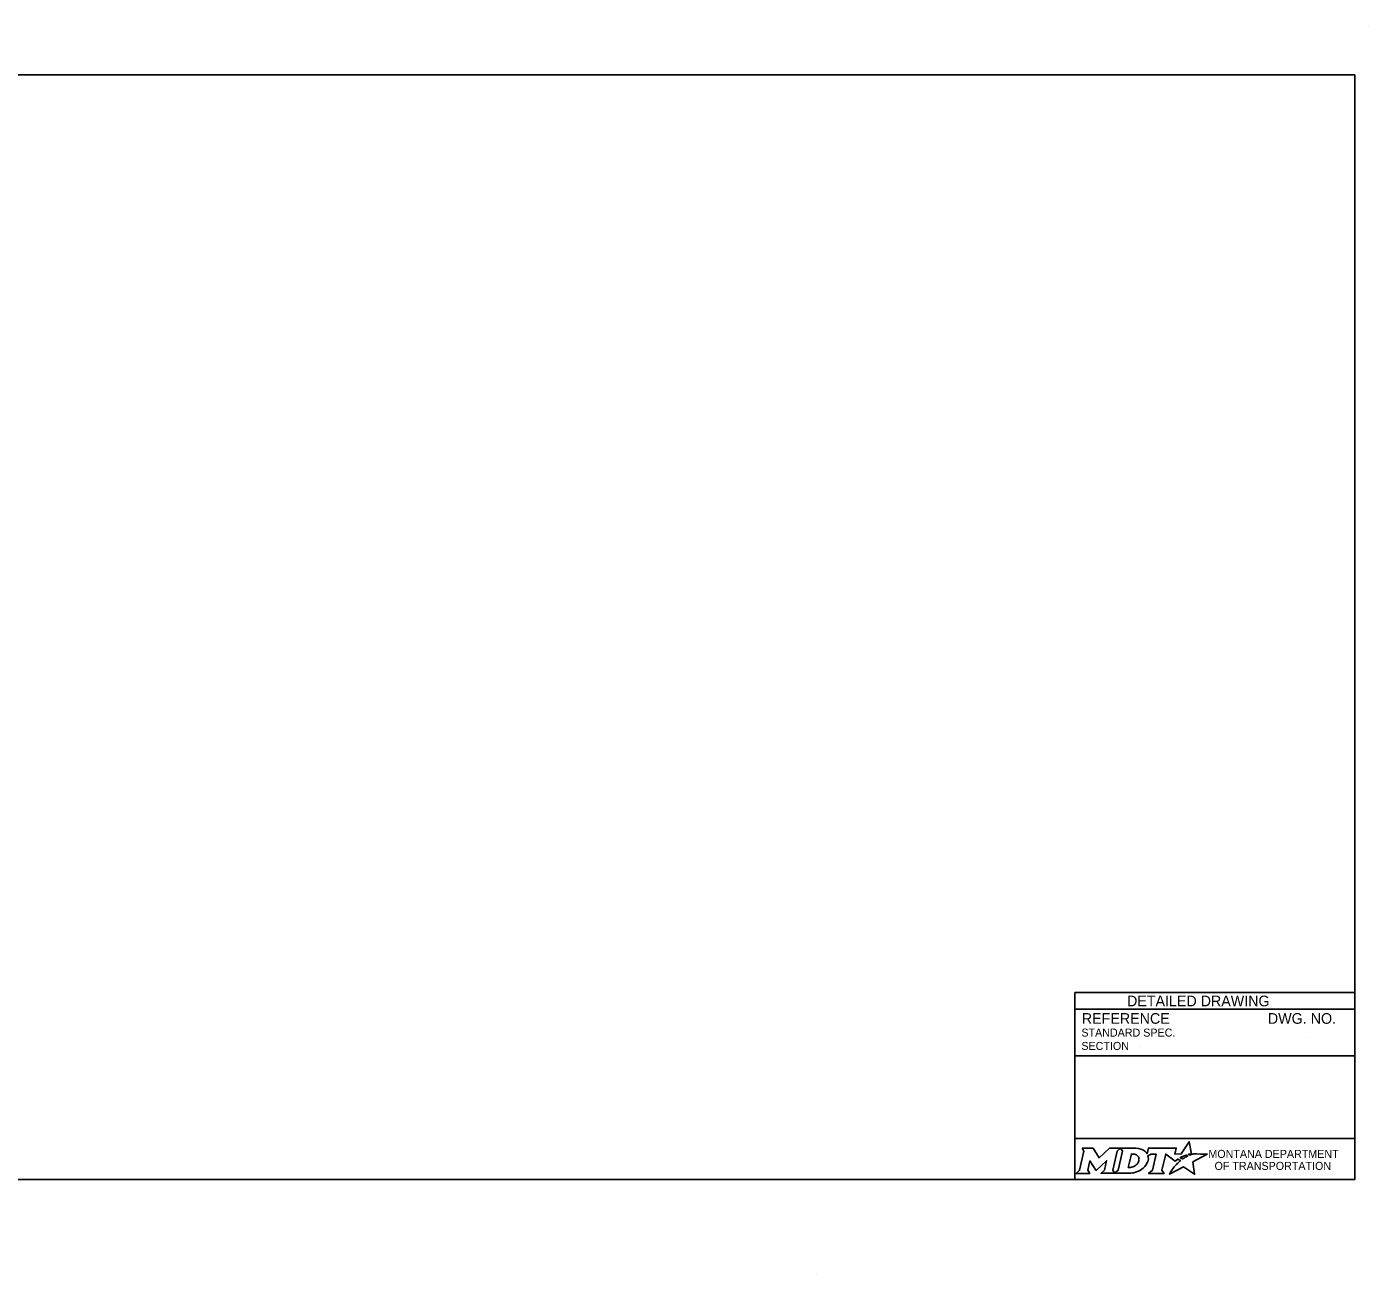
# Model space of a CAD drawing. Extents: x 49991.4 to 50021, y 49987.6 to 50011.4.
# Drawn here: x 50010.98 to 50021.04, y 49999.18 to 50008.52 of the extents above; entities that cross this region are included whole.
import ezdxf

# ---------------------------------------------------------------- set-up
doc = ezdxf.new("R2010")
doc.units = 0
for name, color, linetype in [('Default', 7, 'Continuous'), ('Level 1', 7, 'Continuous'), ('Level 4', 7, 'Continuous')]:
    doc.layers.add(name, color=color, linetype=linetype)

msp = doc.modelspace()

# ---------------------------------------------------------------- linework, layer by layer
at = {"layer": 'Default'}
for points in [[(50018.893, 50000.121), (50018.907, 50000.097), (50018.874, 49999.954), (50018.848, 49999.931), (50018.95, 49999.931), (50018.936, 49999.954), (50018.952, 50000.024), (50018.996, 49999.955), (50019.002, 49999.955), (50019.077, 50000.025), (50019.06, 49999.954), (50019.035, 49999.932), (50019.137, 49999.932), (50019.123, 49999.955), (50019.156, 50000.097)], [(50019.156, 50000.097), (50019.182, 50000.121), (50019.099, 50000.121), (50019.02, 50000.048), (50018.975, 50000.12), (50018.893, 50000.121)], [(50019.295, 50000.121), (50019.182, 50000.121), (50019.196, 50000.098), (50019.163, 49999.954), (50019.137, 49999.932), (50019.248, 49999.932)], [(50019.7, 50000.068), (50019.69, 50000.074), (50019.702, 50000.076), (50019.713, 50000.078), (50019.696, 50000.168), (50019.636, 50000.077), (50019.589, 50000.076), (50019.599, 50000.12), (50019.39, 50000.121), (50019.38, 50000.078), (50019.374, 50000.086)], [(50019.319, 50000.034), (50019.318, 50000.026), (50019.315, 50000.017), (50019.311, 50000.008), (50019.305, 50000.001), (50019.299, 49999.994), (50019.291, 49999.988), (50019.282, 49999.983), (50019.273, 49999.979), (50019.264, 49999.977), (50019.255, 49999.976), (50019.239, 49999.976), (50019.263, 50000.076), (50019.279, 50000.076), (50019.286, 50000.075), (50019.294, 50000.073), (50019.301, 50000.07), (50019.307, 50000.066), (50019.311, 50000.061), (50019.315, 50000.055), (50019.318, 50000.049), (50019.319, 50000.042), (50019.32, 50000.038), (50019.319, 50000.034)], [(50019.387, 50000.062), (50019.411, 50000.075), (50019.448, 50000.075), (50019.42, 49999.954), (50019.392, 49999.931), (50019.508, 49999.931), (50019.491, 49999.954), (50019.52, 50000.075), (50019.591, 50000.023), (50019.612, 50000.038), (50019.632, 50000.027)], [(50019.576, 49999.971), (50019.561, 49999.947), (50019.556, 49999.939), (50019.55, 49999.931), (50019.548, 49999.926), (50019.653, 49999.979), (50019.737, 49999.924), (50019.724, 50000.017), (50019.831, 50000.075), (50019.782, 50000.076), (50019.751, 50000.077), (50019.731, 50000.077), (50019.724, 50000.075), (50019.719, 50000.074), (50019.711, 50000.072), (50019.7, 50000.068)], [(50019.65, 50000.04), (50019.648, 50000.039), (50019.629, 50000.048), (50019.639, 50000.054), (50019.644, 50000.056), (50019.652, 50000.06), (50019.658, 50000.063), (50019.666, 50000.066), (50019.673, 50000.068), (50019.685, 50000.061), (50019.681, 50000.059), (50019.676, 50000.056), (50019.672, 50000.054), (50019.667, 50000.051), (50019.665, 50000.05), (50019.662, 50000.049), (50019.66, 50000.047), (50019.658, 50000.046), (50019.655, 50000.044), (50019.652, 50000.042), (50019.65, 50000.04)], [(50019.293, 49999.939), (50019.302, 49999.942), (50019.315, 49999.947), (50019.335, 49999.958)], [(50019.59, 49999.987), (50019.59, 49999.987)]]:
    msp.add_lwpolyline(points, dxfattribs=at)
for centre, radius, start, end in [((50019.319, 50000.042), 0.0709, 339.5329, 15.8582), ((50019.274, 50000.059), 0.118, 300.9103, 339.1383)]:
    msp.add_arc(centre, radius, start, end, dxfattribs=at)
for centre, major_axis, ratio, start_param, end_param in [((50019.293, 50000.073), (0.0834, -0.0037), 0.568097, 0.61298, 1.570796), ((50019.349, 50000.081), (0.0361, -0.0295), 0.469099, 1.225588, 1.570796), ((50019.621, 50000.017), (-0.0112, -0.0097), 0.021651, 3.157348, 6.283185), ((50019.248, 50000.08), (0, 0.148), 0.987302, 3.139398, 3.456847), ((50019.583, 49999.979), (-0.00694, -0.00806), 0.008222, 0, 3.137361), ((50019.6, 49999.997), (-0.0098, -0.0102), 0.016458, 3.141593, 6.279097)]:
    msp.add_ellipse(centre, major_axis=major_axis, ratio=ratio, start_param=start_param, end_param=end_param, dxfattribs=at)
at = {"layer": 'Level 1'}
for p, q in [((50021.038, 50008.524), (50021.038, 50008.524)), ((50016.9, 49999.176), (50016.9, 49999.176))]:
    msp.add_line(p, q, dxfattribs=at)
msp.add_lwpolyline([(50020.938, 50008.165), (50009.737, 50008.165), (50009.737, 49999.886), (50020.938, 49999.886)], close=True, dxfattribs=at)
at = {"layer": 'Level 4'}
for p, q in [((50020.938, 50001.286), (50018.838, 50001.286)), ((50018.838, 50001.286), (50018.838, 49999.886)), ((50020.938, 50001.161), (50018.838, 50001.161)), ((50020.574, 50000.946), (50020.574, 50000.946)), ((50019.332, 50000.886), (50019.332, 50000.886)), ((50020.938, 50000.811), (50018.838, 50000.811)), ((50019.888, 50000.562), (50019.888, 50000.562)), ((50020.938, 50000.193), (50018.838, 50000.193))]:
    msp.add_line(p, q, dxfattribs=at)

# ---------------------------------------------------------------- texts
at = {"layer": 'Default'}
for s, p in [('MONTANA DEPARTMENT', (50019.84, 50000.047)), ('OF TRANSPORTATION', (50019.886, 49999.957))]:
    msp.add_text(s, height=0.06, rotation=360, dxfattribs=at).set_placement(p)
at = {"layer": 'Level 4'}
for s, height, p in [('DETAILED DRAWING', 0.0799, (50019.23, 50001.183)), ('REFERENCE', 0.08, (50018.891, 50001.052)), ('DWG. NO.', 0.08, (50020.286, 50001.052)), ('STANDARD SPEC.', 0.06, (50018.888, 50000.956)), ('SECTION', 0.06, (50018.888, 50000.856))]:
    msp.add_text(s, height=height, dxfattribs=at).set_placement(p)

doc.saveas('drawing.dxf')
